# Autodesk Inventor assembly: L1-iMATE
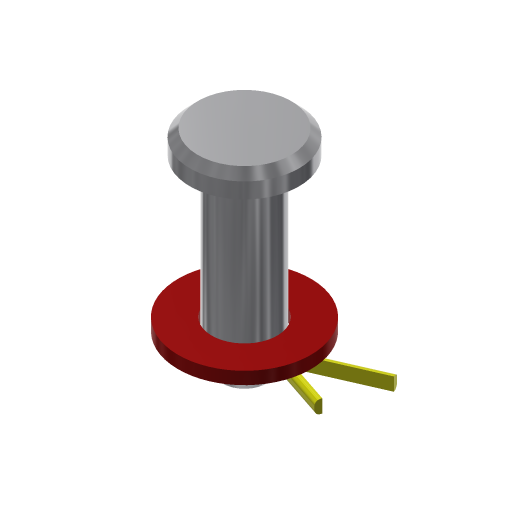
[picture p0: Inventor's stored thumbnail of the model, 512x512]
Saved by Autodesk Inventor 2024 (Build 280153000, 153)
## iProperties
Company: ATC
Created: 2023-03
Part Number: L1-iMATE
Document SubType Name: Assembly
Designer: Andrzej Jaskulski
Checked By: A.J.
Engr Approved By: Andrzej Jaskulski
Mfg Approved By: Andrzej Jaskulski
Authority: A.J.
Title: A.J.: Kurs R2024-MEP
Author: Andrzej Jaskulski
Revision Number: 1/24
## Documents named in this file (4)
- C:\Users\AndJas\Documents\R2024-MEP\Obszar roboczy\L1-iMATE.iam
- C:\Users\AndJas\Documents\R2024-MEP\Pliki Content Center\PN-78_M-82005 - 8,4.ipt
- C:\Users\AndJas\Documents\R2024-MEP\Pliki Content Center\PN-90_M-83002 - B 8x24.ipt
- C:\Users\AndJas\Documents\R2024-MEP\Pliki Content Center\PN-76_M-82001 - 2 x 16.ipt
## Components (3 placed, 3 different names)
1. PN-78/M-82005 8,4:1 — Prześwit
2. PN-90/M-83002 B B 8x24:1 — Położenie poosiowe sworznia:1, Prześwit
3. PN-76/M-82001 2 x 16:1
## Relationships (2: Tangent 1, Mate 1)
- Położenie poosiowe sworznia:1 [Tangent]: PN-90/M-83002 B B 8x24:1
- Prześwit [Mate]: PN-78/M-82005 8,4:1 ↔ PN-90/M-83002 B B 8x24:1
